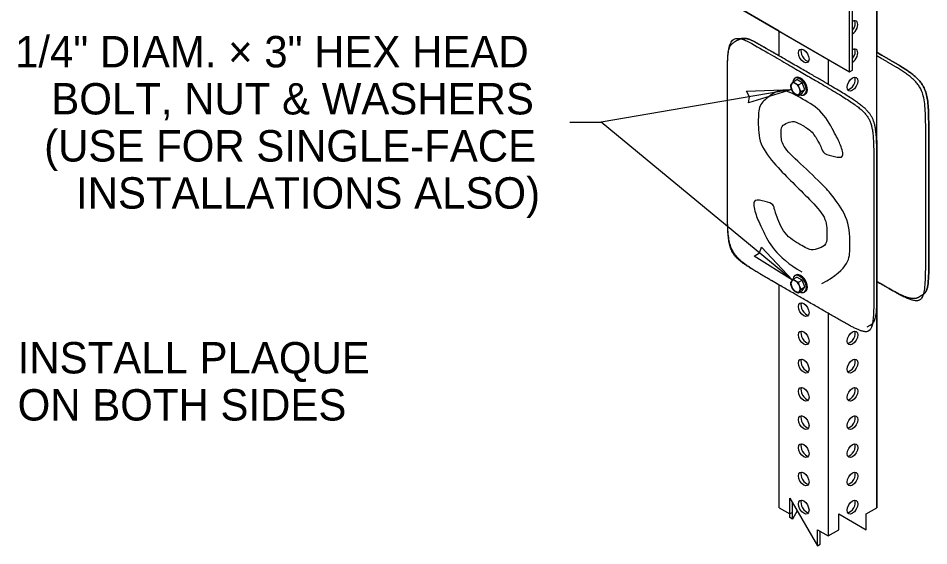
# Model space of a CAD drawing. Extents: x 99862 to 103151, y 100000 to 102076.
# Drawn here: x 102293.6 to 102757.9, y 100777.6 to 101046.5 of the extents above; entities that cross this region are included whole.
import ezdxf

# ---------------------------------------------------------------- set-up
doc = ezdxf.new("R2010")
doc.units = 0
for name, color, linetype in [('Level 15', 7, 'Continuous'), ('Level 2', 7, 'Continuous'), ('Level 20', 7, 'Continuous'), ('Level 9', 7, 'Continuous')]:
    doc.layers.add(name, color=color, linetype=linetype)

msp = doc.modelspace()

# ---------------------------------------------------------------- linework, layer by layer
at = {"layer": 'Level 15'}
for p, q in [((102660.42, 101035.32), (102658.87, 101034.42)), ((102574.8, 100993.45), (102590.8, 100993.45)), ((102754.25, 100905.14), (102752.69, 100904.24)), ((102727.8, 100889.87), (102726.25, 100888.97))]:
    msp.add_line(p, q, dxfattribs=at)
for points, degree in [([(102667.67, 101033.55), (102655.22, 101040.73), (102655.22, 101026.36), (102655.22, 100983.25), (102655.22, 100940.14), (102655.22, 100925.77), (102667.67, 100918.58), (102692.56, 100904.21), (102717.45, 100889.84), (102729.89, 100882.66), (102729.89, 100897.03), (102729.89, 100940.14), (102729.89, 100983.25), (102729.89, 100997.62), (102717.45, 101004.81), (102692.56, 101019.18), (102667.67, 101033.55)], 4), ([(102669.22, 101034.44), (102664.07, 101037.42), (102660.42, 101035.32)], 2), ([(102727.8, 100889.87), (102731.45, 100891.97), (102731.45, 100897.93), (102731.45, 100941.04), (102731.45, 100984.15), (102731.45, 100998.52), (102719, 101005.7), (102694.11, 101020.07), (102669.22, 101034.44)], 4), ([(102754.25, 100905.14), (102757.89, 100907.24), (102757.89, 100913.19), (102757.89, 100956.31), (102757.89, 100999.42), (102757.89, 101013.79), (102745.45, 101020.97), (102738.45, 101025.01), (102731.45, 101029.06)], 4), ([(102731.45, 100912.3), (102737.67, 100908.7), (102743.89, 100905.11), (102756.34, 100897.93), (102756.34, 100912.3), (102756.34, 100955.41), (102756.34, 100998.52), (102756.34, 101012.89), (102743.89, 101020.07), (102737.67, 101023.67), (102731.45, 101027.26)], 4)]:
    msp.add_open_spline(points, degree=degree, dxfattribs=at)
at = {"layer": 'Level 2'}
for p, q in [((102731.45, 100984.15), (102731.45, 101429.63)), ((102681.67, 101027.26), (102681.67, 101039.83)), ((102692.19, 101030.59), (102692.19, 101030.59)), ((102720.93, 101030.59), (102720.93, 101030.59)), ((102706.56, 101025.46), (102706.56, 101012.89)), ((102717.45, 101019.18), (102719, 101020.07)), ((102720.93, 101016.22), (102720.93, 101016.22)), ((102731.45, 100984.15), (102731.45, 100912.3)), ((102681.67, 100797), (102681.67, 100910.5)), ((102706.56, 100896.13), (102706.56, 100782.63)), ((102731.45, 100797), (102731.45, 100897.92)), ((102720.93, 100886.89), (102720.93, 100886.89)), ((102692.19, 100872.52), (102692.19, 100872.52)), ((102720.93, 100872.52), (102720.93, 100872.52)), ((102692.19, 100858.15), (102692.19, 100858.15)), ((102692.19, 100829.41), (102692.19, 100829.41)), ((102720.93, 100829.41), (102720.93, 100829.41)), ((102692.19, 100815.04), (102692.19, 100815.04)), ((102720.93, 100815.04), (102720.93, 100815.04)), ((102688.39, 100794.62), (102688.39, 100799.71)), ((102688.39, 100794.62), (102687.09, 100793.87)), ((102687.09, 100792.01), (102687.09, 100793.87)), ((102688.39, 100791.26), (102687.09, 100792.01)), ((102702.44, 100778.4), (102702.44, 100785)), ((102701.14, 100777.64), (102702.44, 100778.4))]:
    msp.add_line(p, q, dxfattribs=at)
for points in [[(102655.22, 101055.1), (102717.45, 101019.18), (102717.45, 101407.17), (102655.22, 101443.1)], [(102706.56, 101025.46), (102717.45, 101019.18), (102717.45, 101407.17), (102655.22, 101443.1)], [(102681.67, 101429.63), (102706.56, 101444), (102731.45, 101429.63), (102731.45, 101029.06)], [(102681.67, 101027.26), (102681.67, 101039.83), (102655.22, 101055.1)], [(102655.22, 101055.1), (102681.67, 101039.83), (102706.56, 101025.46)], [(102658.87, 101034.42), (102660.42, 101035.32)], [(102689.59, 101015.93), (102690.11, 101016.22)], [(102692.25, 101007.58), (102691.52, 101007.16)], [(102695, 101007.76), (102694.48, 101007.46)], [(102689.59, 100915.33), (102690.11, 100915.63)], [(102681.67, 100797.12), (102681.67, 100910.5)], [(102692.25, 100906.99), (102691.52, 100906.57)], [(102695, 100907.16), (102694.48, 100906.86)], [(102754.25, 100905.14), (102752.69, 100904.24)], [(102731.45, 100897.93), (102731.45, 100797)], [(102681.67, 100797), (102687.09, 100793.87), (102687.09, 100801.98), (102701.14, 100777.64), (102701.14, 100785.76), (102706.56, 100782.63)], [(102690.83, 100795.49), (102688.39, 100791.26), (102688.39, 100794.62)], [(102706.56, 100782.63), (102706.56, 100782.63), (102711.98, 100785.76), (102711.98, 100793.87), (102726.03, 100785.76), (102726.03, 100793.87), (102731.45, 100797)]]:
    msp.add_lwpolyline(points, dxfattribs=at)
for centre, major_axis, start_param, end_param in [((102719, 101041.63), (-1.92, -3.33), 0.785398, 3.926991), ((102717.69, 101042.38), (-1.92, -3.33), 1.286053, 2.795302), ((102695.42, 101028.01), (1.92, -3.33), 3.487884, 5.936894), ((102719, 101027.26), (-1.92, -3.33), 0.785398, 3.926991), ((102717.69, 101028.01), (-1.92, -3.33), 1.286053, 2.795302), ((102692.04, 101011.69), (2.44, -4.23), 3.141593, 3.891684), ((102692.56, 101011.99), (2.44, -4.23), 6.283184, 9.424781), ((102717.69, 101013.64), (-1.92, -3.33), 0.346291, 2.795302), ((102689.96, 101010.51), (1.65, -2.86), 3.3825, 3.424282), ((102689.96, 101010.51), (1.65, -2.86), 4.423348, 4.477829), ((102689.96, 101010.51), (1.65, -2.86), 5.47306, 5.52251), ((102692.04, 101011.69), (2.44, -4.23), 5.560453, 6.283185), ((102692.04, 100911.1), (2.44, -4.23), 3.141593, 3.891684), ((102692.56, 100911.4), (2.44, -4.23), 6.283184, 9.424781), ((102689.96, 100909.92), (1.65, -2.86), 4.423348, 4.477829), ((102689.96, 100909.92), (1.65, -2.86), 3.3825, 3.424282), ((102689.96, 100909.92), (1.65, -2.86), 5.47306, 5.52251), ((102692.04, 100911.1), (2.44, -4.23), 5.560453, 6.283185), ((102695.42, 100898.68), (1.92, -3.33), 3.487884, 5.936894), ((102695.42, 100884.31), (1.92, -3.33), 3.487884, 5.936894), ((102717.69, 100884.31), (-1.92, -3.33), 0.346291, 2.795302), ((102695.42, 100869.94), (1.92, -3.33), 3.487884, 5.936894), ((102717.69, 100869.94), (-1.92, -3.33), 0.346291, 2.795302), ((102695.42, 100855.57), (1.92, -3.33), 3.487884, 5.936894), ((102717.69, 100855.57), (-1.92, -3.33), 0.346291, 2.795302), ((102695.42, 100841.2), (1.92, -3.33), 3.487884, 5.936894), ((102717.69, 100841.2), (-1.92, -3.33), 0.346291, 2.795302), ((102695.42, 100826.83), (1.92, -3.33), 3.487884, 5.936894), ((102717.69, 100826.83), (-1.92, -3.33), 0.346291, 2.795302), ((102695.42, 100812.46), (1.92, -3.33), 3.487884, 5.936894), ((102717.69, 100812.46), (-1.92, -3.33), 0.346291, 2.795302), ((102695.42, 100798.09), (1.92, -3.33), 3.487884, 5.936894), ((102717.69, 100798.09), (-1.92, -3.33), 0.346291, 2.795302)]:
    msp.add_ellipse(centre, major_axis=major_axis, ratio=0.57735, start_param=start_param, end_param=end_param, dxfattribs=at)
for centre, major_axis in [((102694.11, 101027.26), (1.92, -3.33)), ((102719, 101012.89), (-1.92, -3.33)), ((102694.11, 100897.93), (1.92, -3.33)), ((102694.11, 100883.56), (1.92, -3.33)), ((102719, 100883.56), (-1.92, -3.33)), ((102694.11, 100869.19), (1.92, -3.33)), ((102719, 100869.19), (-1.92, -3.33)), ((102694.11, 100854.81), (1.92, -3.33)), ((102719, 100854.81), (-1.92, -3.33)), ((102694.11, 100840.44), (1.92, -3.33)), ((102719, 100840.44), (-1.92, -3.33)), ((102694.11, 100826.07), (1.92, -3.33)), ((102719, 100826.07), (-1.92, -3.33)), ((102694.11, 100811.7), (1.92, -3.33)), ((102719, 100811.7), (-1.92, -3.33)), ((102694.11, 100797.33), (1.92, -3.33)), ((102719, 100797.33), (-1.92, -3.33))]:
    msp.add_ellipse(centre, major_axis=major_axis, ratio=0.57735, dxfattribs=at)
for points, degree in [([(102719, 101020.07), (102719, 101214.07), (102719, 101408.07), (102687.89, 101426.04), (102656.78, 101444), (102607, 101472.74), (102557.22, 101501.48), (102552.06, 101504.46), (102548.42, 101502.35)], 4), ([(102681.67, 100910.5), (102674.67, 100914.54), (102667.67, 100918.58), (102655.22, 100925.77), (102655.22, 100940.14), (102655.22, 100983.25), (102655.22, 101026.36), (102655.22, 101032.31), (102658.87, 101034.42)], 4), ([(102658.87, 101034.42), (102658.87, 101034.42), (102658.87, 101034.42)], 2), ([(102660.42, 101035.32), (102664.07, 101037.42), (102669.22, 101034.44)], 2), ([(102669.22, 101034.44), (102675.44, 101030.85), (102681.67, 101027.26)], 2), ([(102731.45, 101029.06), (102738.45, 101025.01), (102745.45, 101020.97), (102757.89, 101013.79), (102757.89, 100999.42), (102757.89, 100956.31), (102757.89, 100913.19), (102757.89, 100907.24), (102754.25, 100905.14)], 4), ([(102687.48, 101012.19), (102687.57, 101012.42), (102687.7, 101012.68), (102687.92, 101012.99)], 2), ([(102687.91, 101010.41), (102687.7, 101010.98), (102687.57, 101011.57), (102687.48, 101012.19)], 2), ([(102687.97, 101013.06), (102688.14, 101013.3), (102688.35, 101013.55), (102688.58, 101013.83)], 2), ([(102703.41, 100911.24), (102717.64, 100919.19), (102717.64, 100929.7), (102717.64, 100944.11), (102708.54, 100956.1), (102705.74, 100959.88), (102691.62, 100973.15), (102682.64, 100981.57), (102682.64, 100987.63), (102682.64, 100991.8), (102685.85, 100993.12), (102689.06, 100994.43), (102693.61, 100991.8), (102698.62, 100988.91), (102702.01, 100982.64), (102703.06, 100980.69), (102704.22, 100977.19), (102709.76, 100976.01), (102715.31, 100974.83), (102712.86, 100982.31), (102710.64, 100986.55), (102703.99, 100999.28), (102693.61, 101005.28), (102682.87, 101011.47), (102676.34, 101006.49), (102670.97, 101002.45), (102670.97, 100994.36), (102670.97, 100982.24), (102680.07, 100971.19), (102688.47, 100962.7), (102696.99, 100954.28), (102705.97, 100944.92), (102705.97, 100936.43), (102705.97, 100930.78), (102702.01, 100929.29), (102698.04, 100927.81), (102693.14, 100930.64), (102683.69, 100936.1), (102679.72, 100947.55), (102679.14, 100949.37), (102678.55, 100952.26), (102673.01, 100953.44), (102667.47, 100954.62), (102669.8, 100945.73), (102672.25, 100940.54), (102679.72, 100924.92), (102693.14, 100917.17)], 3), ([(102688.82, 101008.71), (102688.49, 101009.18), (102688.2, 101009.69), (102687.97, 101010.25)], 2), ([(102689.91, 101007.85), (102689.48, 101008.1), (102689.12, 101008.4), (102688.82, 101008.71)], 2), ([(102691.52, 101007.16), (102690.98, 101007.33), (102690.46, 101007.53), (102690.02, 101007.78)], 2), ([(102687.48, 100911.59), (102687.57, 100911.82), (102687.7, 100912.08), (102687.92, 100912.4)], 2), ([(102687.91, 100909.82), (102687.7, 100910.39), (102687.57, 100910.98), (102687.48, 100911.59)], 2), ([(102687.97, 100912.47), (102688.14, 100912.7), (102688.35, 100912.96), (102688.58, 100913.23)], 2), ([(102688.82, 100908.12), (102688.49, 100908.59), (102688.2, 100909.1), (102687.97, 100909.65)], 2), ([(102752.69, 100904.24), (102749.05, 100902.13), (102743.89, 100905.11), (102737.67, 100908.7), (102731.45, 100912.3)], 4), ([(102731.45, 100912.3), (102731.45, 100905.11), (102731.45, 100897.93)], 2), ([(102689.91, 100907.26), (102689.48, 100907.51), (102689.12, 100907.81), (102688.82, 100908.12)], 2), ([(102691.52, 100906.57), (102690.98, 100906.74), (102690.46, 100906.94), (102690.02, 100907.19)], 2)]:
    msp.add_open_spline(points, degree=degree, dxfattribs=at)
at = {"layer": 'Level 20'}
for p in [(102688.01, 101010.17), (102688.38, 100913)]:
    msp.add_line(p, (102590.8, 100993.45), dxfattribs=at)
for points in [[(102688.01, 101010.17), (102666.01, 101003.36), (102666.55, 101006.48), (102665, 101009.24)], [(102688.38, 100913), (102668.87, 100925.22), (102671.58, 100926.85), (102672.67, 100929.82)]]:
    msp.add_lwpolyline(points, close=True, dxfattribs=at)
at = {"layer": 'Level 9'}
for p, q in [((102689.59, 101015.93), (102690.11, 101016.22)), ((102687.97, 101013.06), (102687.92, 101012.99)), ((102688.82, 101014.1), (102690.69, 101015.18)), ((102693.38, 101013.62), (102690.69, 101015.18)), ((102691.52, 101012.55), (102693.38, 101013.62)), ((102694.73, 101010.15), (102693.38, 101013.62)), ((102687.91, 101010.41), (102687.97, 101010.25)), ((102689.91, 101007.85), (102690.02, 101007.78)), ((102691.52, 101007.16), (102693.38, 101008.24)), ((102691.97, 101007.97), (102692, 101008.02)), ((102692.87, 101009.07), (102694.73, 101010.15)), ((102693.38, 101008.24), (102694.73, 101010.15)), ((102695, 101007.76), (102694.48, 101007.46)), ((102688.82, 100913.51), (102690.69, 100914.59)), ((102689.59, 100915.33), (102690.11, 100915.63)), ((102693.38, 100913.03), (102690.69, 100914.59)), ((102687.91, 100909.82), (102687.97, 100909.65)), ((102687.97, 100912.47), (102687.92, 100912.4)), ((102691.52, 100911.95), (102693.38, 100913.03)), ((102692.87, 100908.48), (102694.73, 100909.56)), ((102694.73, 100909.56), (102693.38, 100913.03)), ((102693.38, 100907.64), (102694.73, 100909.56)), ((102689.91, 100907.26), (102690.02, 100907.19)), ((102691.52, 100906.57), (102693.38, 100907.64)), ((102691.97, 100907.38), (102692, 100907.43)), ((102695, 100907.16), (102694.48, 100906.86))]:
    msp.add_line(p, q, dxfattribs=at)
for centre, major_axis, start_param, end_param in [((102692.04, 101011.69), (2.44, -4.23), 5.560453, 10.174869), ((102692.56, 101011.99), (2.44, -4.23), 6.283184, 9.424781), ((102689.96, 101010.51), (1.65, -2.86), 2.356194, 8.638997), ((102692.04, 100911.1), (2.44, -4.23), 5.560453, 10.174869), ((102692.56, 100911.4), (2.44, -4.23), 6.283184, 9.424781), ((102689.96, 100909.92), (1.65, -2.86), 2.356194, 8.638997)]:
    msp.add_ellipse(centre, major_axis=major_axis, ratio=0.57735, start_param=start_param, end_param=end_param, dxfattribs=at)
for points, degree in [([(102687.92, 101012.99), (102687.7, 101012.68), (102687.57, 101012.42), (102687.48, 101012.19)], 2), ([(102687.48, 101012.19), (102687.57, 101011.57), (102687.7, 101010.98), (102687.91, 101010.41)], 2), ([(102688.82, 101014.1), (102688.49, 101013.73), (102688.19, 101013.38), (102687.97, 101013.06)], 2), ([(102688.82, 101014.1), (102689.14, 101013.78), (102689.51, 101013.47), (102689.96, 101013.2)], 2), ([(102689.96, 101013.2), (102690.42, 101012.94), (102690.96, 101012.73), (102691.52, 101012.55)], 2), ([(102692.87, 101009.07), (102692.52, 101009.57), (102692.21, 101010.1), (102691.76, 101011.28), (102691.61, 101011.91), (102691.52, 101012.55)], 3), ([(102687.97, 101010.25), (102688.2, 101009.69), (102688.49, 101009.18), (102688.82, 101008.71)], 2), ([(102688.82, 101008.71), (102689.12, 101008.4), (102689.48, 101008.1), (102689.91, 101007.85)], 2), ([(102690.02, 101007.78), (102690.46, 101007.53), (102690.98, 101007.33), (102691.52, 101007.16)], 2), ([(102691.52, 101007.16), (102691.61, 101007.39), (102691.75, 101007.66), (102691.97, 101007.97)], 2), ([(102692, 101008.02), (102692.23, 101008.34), (102692.53, 101008.7), (102692.87, 101009.07)], 2), ([(102688.82, 100913.51), (102688.49, 100913.14), (102688.19, 100912.78), (102687.97, 100912.47)], 2), ([(102688.82, 100913.51), (102689.14, 100913.18), (102689.51, 100912.87), (102689.96, 100912.61)], 2), ([(102687.92, 100912.4), (102687.7, 100912.08), (102687.57, 100911.82), (102687.48, 100911.59)], 2), ([(102687.48, 100911.59), (102687.57, 100910.98), (102687.7, 100910.39), (102687.91, 100909.82)], 2), ([(102687.97, 100909.65), (102688.2, 100909.1), (102688.49, 100908.59), (102688.82, 100908.12)], 2), ([(102689.96, 100912.61), (102690.42, 100912.35), (102690.96, 100912.13), (102691.52, 100911.95)], 2), ([(102692.87, 100908.48), (102692.52, 100908.98), (102692.21, 100909.5), (102691.76, 100910.68), (102691.61, 100911.31), (102691.52, 100911.95)], 3), ([(102688.82, 100908.12), (102689.12, 100907.81), (102689.48, 100907.51), (102689.91, 100907.26)], 2), ([(102690.02, 100907.19), (102690.46, 100906.94), (102690.98, 100906.74), (102691.52, 100906.57)], 2), ([(102691.52, 100906.57), (102691.61, 100906.8), (102691.75, 100907.06), (102691.97, 100907.38)], 2), ([(102692, 100907.43), (102692.23, 100907.75), (102692.53, 100908.1), (102692.87, 100908.48)], 2)]:
    msp.add_open_spline(points, degree=degree, dxfattribs=at)

# ---------------------------------------------------------------- texts
at = {"layer": 'Level 20'}
for s, p in [('1/4" DIAM. × 3" HEX HEAD', (102291.97, 101021.45)), ('BOLT, NUT & WASHERS', (102310.47, 100997.45)), ('(USE FOR SINGLE-FACE', (102306.84, 100973.45)), ('INSTALLATIONS ALSO)', (102323.08, 100949.45)), ('INSTALL PLAQUE', (102293.31, 100865.47)), ('ON BOTH SIDES', (102293.31, 100841.47))]:
    msp.add_text(s, height=16, dxfattribs=at).set_placement(p)

doc.saveas('drawing.dxf')
